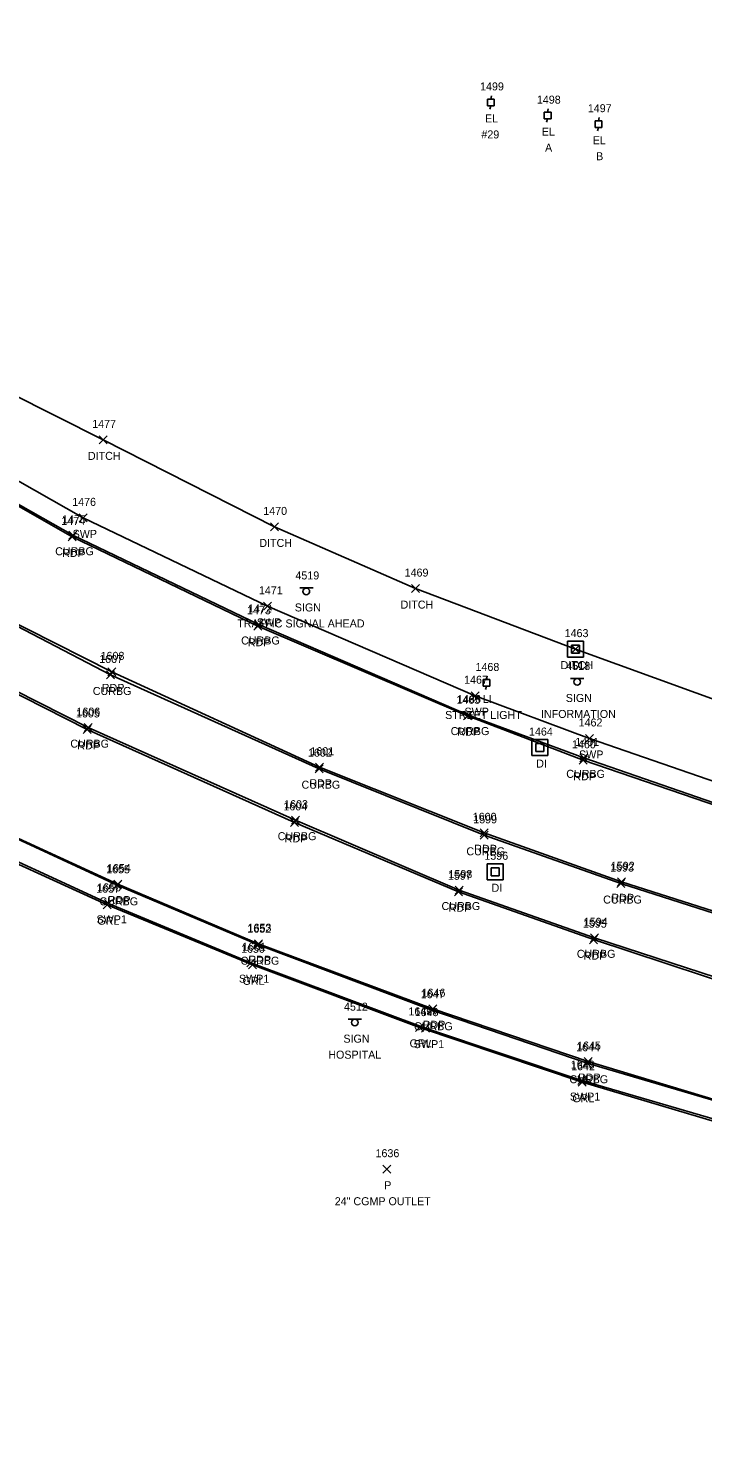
# Model space of a CAD drawing. Extents: x 1690689 to 1696275, y 438760 to 444007.
# Drawn here: x 1692096 to 1692264.7, y 438909.1 to 439260.7 of the extents above; entities that cross this region are included whole.
import ezdxf

# ---------------------------------------------------------------- set-up
doc = ezdxf.new("R2010")
doc.units = 0
for name, color, linetype in [('D_A', 7, 'Continuous'), ('D_C', 7, 'Continuous'), ('D_I', 7, 'Continuous'), ('D_TIC', 7, 'Continuous'), ('DD', 7, 'Continuous'), ('DS', 7, 'Continuous'), ('P_A', 7, 'Continuous'), ('P_I', 7, 'Continuous'), ('P_TIC', 7, 'Continuous'), ('PET', 7, 'Continuous'), ('R_A', 7, 'Continuous'), ('R_I', 7, 'Continuous'), ('R_TIC', 7, 'Continuous'), ('RC', 7, 'Continuous'), ('RGR', 7, 'Continuous'), ('RSW', 7, 'Continuous'), ('S_A', 7, 'Continuous'), ('S_C', 7, 'Continuous'), ('S_I', 7, 'Continuous'), ('SSGN', 7, 'Continuous'), ('U_A', 7, 'Continuous'), ('U_C', 7, 'Continuous'), ('U_I', 7, 'Continuous'), ('UEPT', 7, 'Continuous'), ('ULP', 7, 'Continuous')]:
    doc.layers.add(name, color=color, linetype=linetype)

msp = doc.modelspace()

# ---------------------------------------------------------------- linework, layer by layer
at = {"layer": 'D_TIC'}
for points in [[(1692113.74, 439156.79), (1692115.74, 439158.79)], [(1692115.74, 439156.79), (1692113.74, 439158.79)], [(1692156.57, 439135.03), (1692158.57, 439137.03)], [(1692158.57, 439135.03), (1692156.57, 439137.03)], [(1692191.88, 439119.62), (1692193.88, 439121.62)], [(1692193.88, 439119.62), (1692191.88, 439121.62)], [(1692231.86, 439104.49), (1692233.86, 439106.49)], [(1692233.86, 439104.49), (1692231.86, 439106.49)], [(1692184.65, 438974.51), (1692186.65, 438976.51)], [(1692186.65, 438974.51), (1692184.65, 438976.51)]]:
    msp.add_lwpolyline(points, dxfattribs=at)
at = {"layer": 'DD'}
msp.add_lwpolyline([(1692601.69, 439017.79), (1692563.37, 439021.21), (1692508.43, 439031.44), (1692465.47, 439040.14), (1692415.19, 439051.66), (1692376.4, 439060.91), (1692339.07, 439071.12), (1692282.68, 439087.44), (1692232.86, 439105.49), (1692192.88, 439120.62), (1692157.57, 439136.03), (1692114.74, 439157.79), (1692067.68, 439181.46), (1692012.38, 439226.11), (1692016.4, 439238.61), (1692018.77, 439248.28), (1692013.27, 439253.9), (1692009.52, 439256.4)], dxfattribs=at)
at = {"layer": 'DS'}
for p, q in [((1692230.86, 439107.49), (1692234.86, 439107.49)), ((1692230.86, 439103.49), (1692230.86, 439107.49)), ((1692231.86, 439104.49), (1692231.86, 439106.49)), ((1692231.86, 439106.49), (1692233.86, 439106.49)), ((1692233.86, 439106.49), (1692233.86, 439104.49)), ((1692234.86, 439107.49), (1692234.86, 439103.49)), ((1692234.86, 439103.49), (1692230.86, 439103.49)), ((1692233.86, 439104.49), (1692231.86, 439104.49)), ((1692232.86, 439105.49), (1692232.86, 439105.49)), ((1692232.86, 439105.49), (1692232.86, 439105.49)), ((1692221.95, 439082.89), (1692225.95, 439082.89)), ((1692221.95, 439078.89), (1692221.95, 439082.89)), ((1692222.95, 439079.89), (1692222.95, 439081.89)), ((1692222.95, 439081.89), (1692224.95, 439081.89)), ((1692224.95, 439081.89), (1692224.95, 439079.89)), ((1692225.95, 439082.89), (1692225.95, 439078.89)), ((1692225.95, 439078.89), (1692221.95, 439078.89)), ((1692224.95, 439079.89), (1692222.95, 439079.89)), ((1692223.95, 439080.89), (1692223.95, 439080.89)), ((1692223.95, 439080.89), (1692223.95, 439080.89)), ((1692210.79, 439051.85), (1692214.79, 439051.85)), ((1692210.79, 439047.85), (1692210.79, 439051.85)), ((1692211.79, 439048.85), (1692211.79, 439050.85)), ((1692211.79, 439050.85), (1692213.79, 439050.85)), ((1692212.79, 439049.85), (1692212.79, 439049.85)), ((1692212.79, 439049.85), (1692212.79, 439049.85)), ((1692213.79, 439050.85), (1692213.79, 439048.85)), ((1692214.79, 439051.85), (1692214.79, 439047.85)), ((1692214.79, 439047.85), (1692210.79, 439047.85)), ((1692213.79, 439048.85), (1692211.79, 439048.85))]:
    msp.add_line(p, q, dxfattribs=at)
at = {"layer": 'P_TIC'}
for points in [[(1692106.02, 439132.53), (1692108.02, 439134.53)], [(1692108.02, 439132.53), (1692106.02, 439134.53)], [(1692152.42, 439110.21), (1692154.42, 439112.21)], [(1692154.42, 439110.21), (1692152.42, 439112.21)], [(1692115.96, 439098.81), (1692117.96, 439100.81)], [(1692117.96, 439098.81), (1692115.96, 439100.81)], [(1692204.8, 439087.84), (1692206.8, 439089.84)], [(1692206.8, 439087.84), (1692204.8, 439089.84)], [(1692109.81, 439084.42), (1692111.81, 439086.42)], [(1692111.81, 439084.42), (1692109.81, 439086.42)], [(1692233.78, 439076.7), (1692235.78, 439078.7)], [(1692235.78, 439076.7), (1692233.78, 439078.7)], [(1692167.81, 439074.98), (1692169.81, 439076.98)], [(1692169.81, 439074.98), (1692167.81, 439076.98)], [(1692161.64, 439061.19), (1692163.64, 439063.19)], [(1692163.64, 439061.19), (1692161.64, 439063.19)], [(1692209.04, 439058.59), (1692211.04, 439060.59)], [(1692211.04, 439058.59), (1692209.04, 439060.59)], [(1692117.48, 439045.77), (1692119.48, 439047.77)], [(1692119.48, 439045.77), (1692117.48, 439047.77)], [(1692243.35, 439046.34), (1692245.35, 439048.34)], [(1692245.35, 439046.34), (1692243.35, 439048.34)], [(1692202.62, 439043.85), (1692204.62, 439045.85)], [(1692204.62, 439043.85), (1692202.62, 439045.85)], [(1692152.62, 439030.87), (1692154.62, 439032.87)], [(1692154.62, 439030.87), (1692152.62, 439032.87)], [(1692236.36, 439031.88), (1692238.36, 439033.88)], [(1692238.36, 439031.88), (1692236.36, 439033.88)], [(1692196.17, 439014.62), (1692198.17, 439016.62)], [(1692198.17, 439014.62), (1692196.17, 439016.62)], [(1692234.97, 439001.41), (1692236.97, 439003.41)], [(1692236.97, 439001.41), (1692234.97, 439003.41)]]:
    msp.add_lwpolyline(points, dxfattribs=at)
at = {"layer": 'PET'}
for points in [[(1692506.42, 439007.58), (1692409.86, 439027.99), (1692378.72, 439035.13), (1692333.82, 439046.83), (1692278.1, 439062.9), (1692234.78, 439077.7), (1692205.8, 439088.84), (1692153.42, 439111.21), (1692107.02, 439133.53), (1692055.61, 439162.86), (1692031.29, 439179.06), (1692011.62, 439193.84), (1692002.42, 439202.85), (1692001.04, 439204.48), (1691998.47, 439209.28), (1691996.33, 439214.88), (1691994.6, 439223.82), (1691994.86, 439229.58), (1691997.14, 439239.21), (1692003.46, 439250.16), (1692011.11, 439259.34), (1692010.11, 439260.69)], [(1692765.95, 438921.86), (1692671.87, 438941.97), (1692616.75, 438954.47), (1692587.11, 438960.22), (1692543.54, 438967.18), (1692506.54, 438970.09), (1692469.43, 438975.08), (1692419.94, 438983.98), (1692360.97, 438996.85), (1692305.33, 439011.12), (1692283.25, 439017.76), (1692237.36, 439032.88), (1692203.62, 439044.85), (1692162.64, 439062.19), (1692110.81, 439085.42), (1692073.76, 439104.17), (1692029.3, 439128.96), (1692004.08, 439144.9), (1691989.31, 439154.72), (1691981.95, 439161.75), (1691978.54, 439168.17), (1691978.42, 439170.83), (1691980.54, 439171.6)], [(1692767.64, 438925.55), (1692673.48, 438945.69), (1692617.32, 438957.74), (1692543.2, 438973.83), (1692470.55, 438989.57), (1692418.41, 439000.55), (1692365.96, 439012.47), (1692309.7, 439026.97), (1692288.49, 439033.25), (1692244.35, 439047.34), (1692210.04, 439059.59), (1692168.81, 439075.98), (1692116.96, 439099.81), (1692081.46, 439117.73), (1692037.17, 439142.63), (1692008.65, 439160.43), (1691998.95, 439166.12), (1691980.54, 439171.6)], [(1692485.07, 438945.57), (1692435.03, 438955.4), (1692385.23, 438965.25), (1692340.43, 438974.31), (1692296.87, 438984.77), (1692272.43, 438991.45), (1692235.97, 439002.41), (1692197.17, 439015.62), (1692153.62, 439031.87), (1692118.48, 439046.77), (1692081.06, 439063.89), (1692043.59, 439082.96), (1692015.06, 439098.81), (1691980.04, 439119.84), (1691962.57, 439130.66), (1691955.71, 439134.26), (1691947.97, 439136.72), (1691941.75, 439137.91), (1691935.77, 439138.24), (1691931.84, 439138.11), (1691929.14, 439137.6), (1691914.86, 439134.28)]]:
    msp.add_lwpolyline(points, dxfattribs=at)
at = {"layer": 'R_TIC'}
for points in [[(1692108.79, 439137.3), (1692110.79, 439139.3)], [(1692110.79, 439137.3), (1692108.79, 439139.3)], [(1692106.21, 439132.95), (1692108.21, 439134.95)], [(1692108.21, 439132.95), (1692106.21, 439134.95)], [(1692154.83, 439115.19), (1692156.83, 439117.19)], [(1692156.83, 439115.19), (1692154.83, 439117.19)], [(1692152.68, 439110.65), (1692154.68, 439112.65)], [(1692154.68, 439110.65), (1692152.68, 439112.65)], [(1692115.61, 439098.03), (1692117.61, 439100.03)], [(1692117.61, 439098.03), (1692115.61, 439100.03)], [(1692206.73, 439092.85), (1692208.73, 439094.85)], [(1692208.73, 439092.85), (1692206.73, 439094.85)], [(1692205.05, 439088.01), (1692207.05, 439090.01)], [(1692207.05, 439088.01), (1692205.05, 439090.01)], [(1692109.99, 439084.87), (1692111.99, 439086.87)], [(1692111.99, 439084.87), (1692109.99, 439086.87)], [(1692235.35, 439082.17), (1692237.35, 439084.17)], [(1692237.35, 439082.17), (1692235.35, 439084.17)], [(1692233.93, 439077.32), (1692235.93, 439079.32)], [(1692235.93, 439077.32), (1692233.93, 439079.32)], [(1692167.78, 439074.61), (1692169.78, 439076.61)], [(1692169.78, 439074.61), (1692167.78, 439076.61)], [(1692161.83, 439061.74), (1692163.83, 439063.74)], [(1692163.83, 439061.74), (1692161.83, 439063.74)], [(1692208.98, 439057.96), (1692210.98, 439059.96)], [(1692210.98, 439057.96), (1692208.98, 439059.96)], [(1692117.26, 439045.46), (1692119.26, 439047.46)], [(1692119.26, 439045.46), (1692117.26, 439047.46)], [(1692202.77, 439044.28), (1692204.77, 439046.28)], [(1692204.77, 439044.28), (1692202.77, 439046.28)], [(1692243.17, 439045.9), (1692245.17, 439047.9)], [(1692245.17, 439045.9), (1692243.17, 439047.9)], [(1692114.78, 439040.61), (1692116.78, 439042.61)], [(1692116.78, 439040.61), (1692114.78, 439042.61)], [(1692115.08, 439040.96), (1692117.08, 439042.96)], [(1692117.08, 439040.96), (1692115.08, 439042.96)], [(1692152.55, 439030.62), (1692154.55, 439032.62)], [(1692154.55, 439030.62), (1692152.55, 439032.62)], [(1692236.58, 439032.34), (1692238.58, 439034.34)], [(1692238.58, 439032.34), (1692236.58, 439034.34)], [(1692150.68, 439026.12), (1692152.68, 439028.12)], [(1692152.68, 439026.12), (1692150.68, 439028.12)], [(1692151.08, 439025.6), (1692153.08, 439027.6)], [(1692153.08, 439025.6), (1692151.08, 439027.6)], [(1692195.89, 439014.24), (1692197.89, 439016.24)], [(1692197.89, 439014.24), (1692195.89, 439016.24)], [(1692192.82, 439009.96), (1692194.82, 439011.96)], [(1692194.82, 439009.96), (1692192.82, 439011.96)], [(1692194.38, 439009.77), (1692196.38, 439011.77)], [(1692196.38, 439009.77), (1692194.38, 439011.77)], [(1692234.74, 439000.99), (1692236.74, 439002.99)], [(1692236.74, 439000.99), (1692234.74, 439002.99)], [(1692233.38, 438996.66), (1692235.38, 438998.66)], [(1692235.38, 438996.66), (1692233.38, 438998.66)], [(1692233.48, 438996.25), (1692235.48, 438998.25)], [(1692235.48, 438996.25), (1692233.48, 438998.25)]]:
    msp.add_lwpolyline(points, dxfattribs=at)
at = {"layer": 'RC'}
for points in [[(1692458.66, 439018.07), (1692409.83, 439028.32), (1692378.84, 439035.52), (1692333.85, 439047.39), (1692278.2, 439063.36), (1692234.93, 439078.32), (1692206.05, 439089.01), (1692153.68, 439111.65), (1692107.21, 439133.95), (1692055.41, 439163.27), (1692031.04, 439179.71), (1692011.71, 439194.03), (1692002.37, 439202.91), (1692001.39, 439204.32), (1691998.83, 439209.21), (1691996.61, 439215.03), (1691994.98, 439223.75), (1691995.26, 439229.27), (1691997.49, 439239.08), (1692003.79, 439249.87), (1692007.64, 439254.1)], [(1692766.36, 438922.45), (1692671.96, 438942.46), (1692616.73, 438954.89), (1692587.1, 438960.64), (1692543.8, 438967.52), (1692506.49, 438970.64), (1692469.42, 438975.23), (1692419.64, 438984.49), (1692361.22, 438997.2), (1692305.35, 439011.89), (1692283.35, 439018.43), (1692237.58, 439033.34), (1692203.77, 439045.28), (1692162.83, 439062.74), (1692110.99, 439085.87), (1692073.96, 439104.65), (1692029.68, 439129.43), (1692004.27, 439145.41), (1691989.92, 439155.3), (1691982.48, 439162.24), (1691979.04, 439168.18), (1691978.75, 439170.84), (1691980.34, 439171.05)], [(1692767.42, 438924.95), (1692673.21, 438945.2), (1692617.12, 438957.34), (1692543.19, 438973.28), (1692470.51, 438988.93), (1692418.35, 439000.23), (1692365.64, 439012.16), (1692309.62, 439026.54), (1692288.66, 439032.69), (1692244.17, 439046.9), (1692209.98, 439058.96), (1692168.78, 439075.61), (1692116.61, 439099.03), (1692081.37, 439117.41), (1692037.02, 439142.1), (1692008.48, 439159.75), (1691998.71, 439165.65), (1691980.34, 439171.05)], [(1692485.06, 438945.4), (1692435.02, 438955.15), (1692385.25, 438965.09), (1692340.44, 438973.91), (1692296.71, 438984.59), (1692272.47, 438991.18), (1692235.74, 439001.99), (1692196.89, 439015.24), (1692153.55, 439031.62), (1692118.26, 439046.46), (1692080.62, 439063.88)]]:
    msp.add_lwpolyline(points, dxfattribs=at)
at = {"layer": 'RGR'}
msp.add_lwpolyline([(1692484.4, 438940.25), (1692434.24, 438950.09), (1692384.35, 438959.68), (1692337.49, 438969.42), (1692295.18, 438979.82), (1692270.91, 438986.42), (1692234.48, 438997.25), (1692193.82, 439010.96), (1692152.08, 439026.6), (1692115.78, 439041.61), (1692078.11, 439058.76)], dxfattribs=at)
at = {"layer": 'RSW'}
for points in [[(1692665.59, 438979.47), (1692633.47, 438986.11), (1692606.01, 438992.31), (1692555.68, 439002.49), (1692507.66, 439012.62), (1692459.75, 439022.83), (1692410.78, 439033.39), (1692380.42, 439040.26), (1692334.91, 439052.16), (1692279.52, 439068.27), (1692236.35, 439083.17), (1692207.73, 439093.85), (1692155.83, 439116.19), (1692109.79, 439138.3), (1692057.98, 439167.75), (1692033.9, 439183.79), (1692014.53, 439197.98), (1692008.04, 439204.8), (1692006.24, 439207.82), (1692001.39, 439204.32)], [(1692637.9, 438909.12), (1692604.66, 438916.25), (1692559.9, 438925.87), (1692526.71, 438932.34), (1692484.3, 438940.72), (1692434.26, 438950.4), (1692384.3, 438960.21), (1692339.45, 438969.35), (1692295.64, 438980.27), (1692271.48, 438986.87), (1692234.38, 438997.66), (1692195.38, 439010.77), (1692151.68, 439027.12), (1692116.08, 439041.96), (1692078.43, 439059.23), (1692041.02, 439078.87), (1692012.59, 439094.44), (1691977.25, 439115.7), (1691958.72, 439127.11), (1691952.86, 439130.25), (1691946.68, 439131.94), (1691948, 439136.19)]]:
    msp.add_lwpolyline(points, dxfattribs=at)
at = {"layer": 'SSGN'}
for p, q in [((1692163.9, 439120.77), (1692167.23, 439120.77)), ((1692165.55, 439119.93), (1692165.55, 439119.93)), ((1692231.62, 439098.14), (1692234.95, 439098.14)), ((1692233.26, 439097.31), (1692233.26, 439097.31)), ((1692176.03, 439012.99), (1692179.37, 439012.99)), ((1692177.68, 439012.16), (1692177.68, 439012.16))]:
    msp.add_line(p, q, dxfattribs=at)
for centre in [(1692165.55, 439119.93), (1692233.26, 439097.31), (1692177.68, 439012.16)]:
    msp.add_circle(centre, 0.833, dxfattribs=at)
at = {"layer": 'UEPT'}
for p, q in [((1692210.85, 439241.3), (1692210.85, 439242.96)), ((1692210.85, 439242.96), (1692212.52, 439242.96)), ((1692211.85, 439243.8), (1692211.68, 439242.96)), ((1692212.52, 439242.96), (1692212.52, 439241.3)), ((1692212.52, 439241.3), (1692210.85, 439241.3)), ((1692211.43, 439240.46), (1692211.68, 439241.3)), ((1692211.68, 439242.13), (1692211.68, 439242.13)), ((1692225.04, 439237.99), (1692225.04, 439239.66)), ((1692225.04, 439239.66), (1692226.71, 439239.66)), ((1692226.04, 439240.49), (1692225.87, 439239.66)), ((1692226.71, 439239.66), (1692226.71, 439237.99)), ((1692226.71, 439237.99), (1692225.04, 439237.99)), ((1692225.62, 439237.16), (1692225.87, 439237.99)), ((1692225.87, 439238.82), (1692225.87, 439238.82)), ((1692237.77, 439235.84), (1692237.77, 439237.51)), ((1692237.77, 439237.51), (1692239.44, 439237.51)), ((1692238.77, 439238.34), (1692238.6, 439237.51)), ((1692238.6, 439236.68), (1692238.6, 439236.68)), ((1692239.44, 439237.51), (1692239.44, 439235.84)), ((1692239.44, 439235.84), (1692237.77, 439235.84)), ((1692238.35, 439235.01), (1692238.6, 439235.84))]:
    msp.add_line(p, q, dxfattribs=at)
at = {"layer": 'ULP'}
for p, q in [((1692209.75, 439096.21), (1692209.75, 439097.87)), ((1692209.75, 439097.87), (1692211.42, 439097.87)), ((1692211.42, 439096.21), (1692209.75, 439096.21)), ((1692210.33, 439095.37), (1692210.58, 439096.21)), ((1692210.75, 439098.71), (1692210.58, 439097.87)), ((1692210.58, 439097.04), (1692210.58, 439097.04)), ((1692211.42, 439097.87), (1692211.42, 439096.21))]:
    msp.add_line(p, q, dxfattribs=at)

# ---------------------------------------------------------------- texts
at = {"layer": 'D_A'}
for s, p in [('DITCH', (1692110.97, 439152.79)), ('DITCH', (1692153.81, 439131.03)), ('DITCH', (1692189.11, 439115.62)), ('DITCH', (1692229.1, 439100.49)), ('DI', (1692231.92, 439100.49)), ('DI', (1692223.01, 439075.89)), ('DI', (1692211.85, 439044.85)), ('P', (1692185.03, 438970.51))]:
    msp.add_text(s, height=2, dxfattribs=at).set_placement(p)
at = {"layer": 'D_C'}
msp.add_text('24" CGMP OUTLET', height=2, dxfattribs=at).set_placement((1692172.66, 438966.51))
at = {"layer": 'D_I'}
for s, p in [('1477', (1692112.04, 439160.79)), ('1470', (1692154.79, 439139.03)), ('1469', (1692190.13, 439123.62)), ('1463', (1692230.12, 439108.49)), ('1463', (1692230.12, 439108.49)), ('1464', (1692221.21, 439083.89)), ('1596', (1692210.05, 439052.85)), ('1636', (1692182.85, 438978.51))]:
    msp.add_text(s, height=2, dxfattribs=at).set_placement(p)
at = {"layer": 'P_A'}
for p in [(1692104.51, 439128.53), (1692150.9, 439106.21), (1692114.45, 439094.81), (1692203.28, 439083.84), (1692108.3, 439080.42), (1692232.27, 439072.7), (1692166.3, 439070.98), (1692160.12, 439057.19), (1692207.53, 439054.59), (1692115.97, 439041.77), (1692241.84, 439042.34), (1692201.11, 439039.85), (1692151.11, 439026.87), (1692234.85, 439027.88), (1692194.65, 439010.62), (1692233.45, 438997.41)]:
    msp.add_text('RDP', height=2, dxfattribs=at).set_placement(p)
at = {"layer": 'P_I'}
for s, p in [('1474', (1692104.32, 439136.53)), ('1473', (1692150.72, 439114.21)), ('1608', (1692114.14, 439102.81)), ('1465', (1692203.06, 439091.84)), ('1605', (1692107.99, 439088.42)), ('1460', (1692231.95, 439080.7)), ('1601', (1692166.56, 439078.98)), ('1604', (1692159.82, 439065.19)), ('1600', (1692207.14, 439062.59)), ('1654', (1692115.74, 439049.77)), ('1597', (1692200.93, 439047.85)), ('1592', (1692241.66, 439050.34)), ('1653', (1692150.88, 439034.87)), ('1595', (1692234.67, 439035.88)), ('1646', (1692194.37, 439018.62)), ('1645', (1692233.23, 439005.41))]:
    msp.add_text(s, height=2, dxfattribs=at).set_placement(p)
at = {"layer": 'R_A'}
for s, p in [('SWP', (1692107.15, 439133.3)), ('CURBG', (1692102.79, 439128.95)), ('SWP', (1692153.19, 439111.19)), ('CURBG', (1692149.26, 439106.65)), ('CURBG', (1692112.19, 439094.03)), ('SWP', (1692205.09, 439088.85)), ('CURBG', (1692201.63, 439084.01)), ('CURBG', (1692106.57, 439080.87)), ('SWP', (1692233.72, 439078.17)), ('CURBG', (1692230.52, 439073.32)), ('CURBG', (1692164.36, 439070.61)), ('CURBG', (1692158.41, 439057.74)), ('CURBG', (1692205.56, 439053.96)), ('CURBG', (1692113.84, 439041.46)), ('CURBG', (1692239.75, 439041.9)), ('CURBG', (1692199.35, 439040.28)), ('SWP1', (1692113.12, 439036.96)), ('GRL', (1692113.32, 439036.61)), ('CURBG', (1692149.13, 439026.62)), ('CURBG', (1692233.16, 439028.34)), ('SWP1', (1692148.72, 439022.12)), ('GRL', (1692149.62, 439021.6)), ('CURBG', (1692192.47, 439010.24)), ('GRL', (1692191.36, 439005.96)), ('SWP1', (1692192.42, 439005.77)), ('CURBG', (1692231.32, 438996.99)), ('SWP1', (1692231.42, 438992.66)), ('GRL', (1692232.03, 438992.25))]:
    msp.add_text(s, height=2, dxfattribs=at).set_placement(p)
at = {"layer": 'R_I'}
for s, p in [('1476', (1692107.04, 439141.3)), ('1475', (1692104.52, 439136.95)), ('1471', (1692153.7, 439119.19)), ('1472', (1692150.99, 439114.65)), ('1607', (1692113.79, 439102.03)), ('1467', (1692204.99, 439096.85)), ('1466', (1692203.26, 439092.01)), ('1606', (1692108.11, 439088.87)), ('1462', (1692233.61, 439086.17)), ('1461', (1692232.76, 439081.32)), ('1602', (1692165.96, 439078.61)), ('1603', (1692160.01, 439065.74)), ('1599', (1692207.27, 439061.96)), ('1655', (1692115.52, 439049.46)), ('1598', (1692201.08, 439048.28)), ('1593', (1692241.48, 439049.9)), ('1657', (1692113.04, 439044.61)), ('1656', (1692113.28, 439044.96)), ('1652', (1692150.81, 439034.62)), ('1594', (1692234.89, 439036.34)), ('1651', (1692149.51, 439030.12)), ('1650', (1692149.25, 439029.6)), ('1647', (1692194.15, 439018.24)), ('1649', (1692191.07, 439013.96)), ('1648', (1692192.64, 439013.77)), ('1644', (1692233, 439004.99)), ('1643', (1692231.64, 439000.66)), ('1642', (1692231.74, 439000.25))]:
    msp.add_text(s, height=2, dxfattribs=at).set_placement(p)
at = {"layer": 'S_A'}
for p in [(1692162.68, 439114.91), (1692230.4, 439092.29), (1692174.82, 439007.14)]:
    msp.add_text('SIGN', height=2, dxfattribs=at).set_placement(p)
at = {"layer": 'S_C'}
for s, p in [('TRAFFIC SIGNAL AHEAD', (1692148.31, 439110.91)), ('INFORMATION', (1692224.2, 439088.29)), ('HOSPITAL', (1692171.05, 439003.14))]:
    msp.add_text(s, height=2, dxfattribs=at).set_placement(p)
at = {"layer": 'S_I'}
for s, p in [('4519', (1692162.83, 439122.91)), ('4518', (1692230.55, 439100.29)), ('4512', (1692174.97, 439015.14))]:
    msp.add_text(s, height=2, dxfattribs=at).set_placement(p)
at = {"layer": 'U_A'}
for s, p in [('EL', (1692210.22, 439237.13)), ('EL', (1692224.41, 439233.82)), ('EL', (1692237.14, 439231.68)), ('LI', (1692209.68, 439092.04))]:
    msp.add_text(s, height=2, dxfattribs=at).set_placement(p)
at = {"layer": 'U_C'}
for s, p in [('#29', (1692209.31, 439233.13)), ('A', (1692225.22, 439229.82)), ('B', (1692237.98, 439227.68)), ('STREET LIGHT', (1692200.24, 439088.04))]:
    msp.add_text(s, height=2, dxfattribs=at).set_placement(p)
at = {"layer": 'U_I'}
for s, p in [('1499', (1692208.98, 439245.13)), ('1498', (1692223.18, 439241.82)), ('1497', (1692235.91, 439239.68)), ('1468', (1692207.84, 439100.04))]:
    msp.add_text(s, height=2, dxfattribs=at).set_placement(p)

doc.saveas('drawing.dxf')
